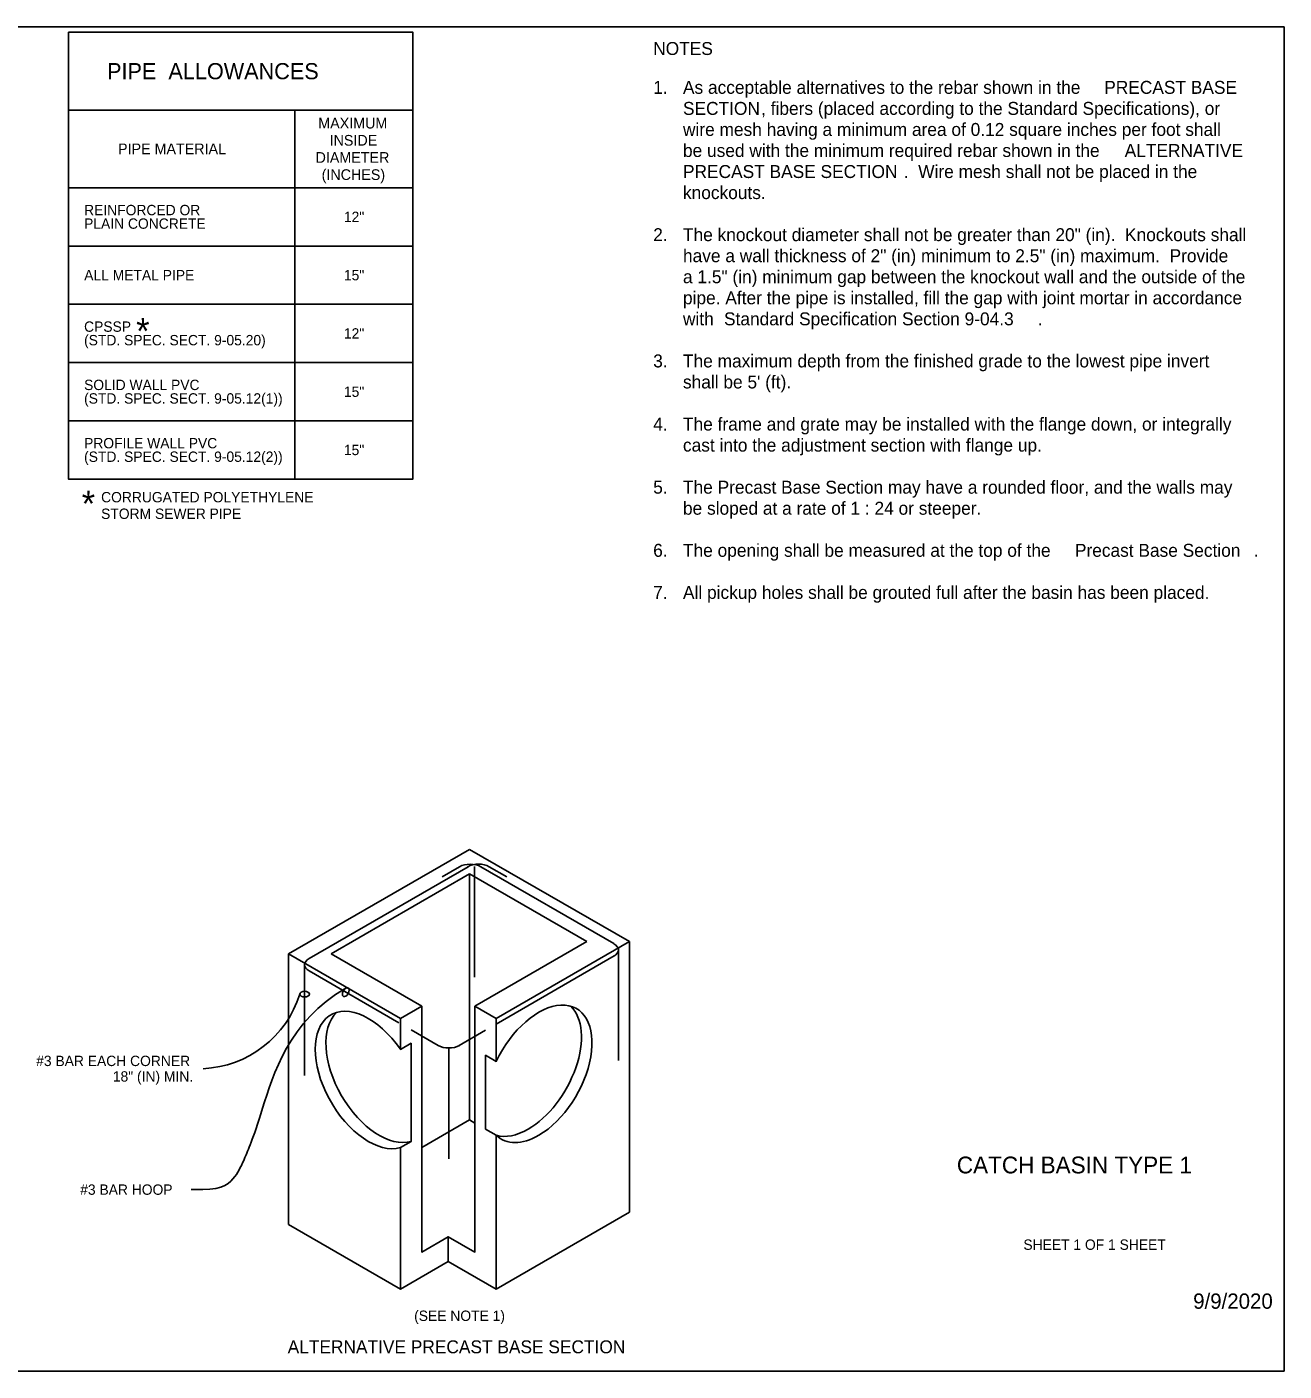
# Model space of a CAD drawing. Extents: x 99862 to 103151, y 100000 to 102076.
# Drawn here: x 101209 to 103151, y 100000 to 102076 of the extents above; entities that cross this region are included whole.
import ezdxf

# ---------------------------------------------------------------- set-up
doc = ezdxf.new("R2010")
doc.units = 0
for name, color, linetype in [('Level 1', 7, 'Continuous'), ('Level 15', 7, 'Continuous'), ('Level 17', 7, 'Continuous'), ('Level 19', 7, 'Continuous'), ('Level 20', 7, 'Continuous'), ('Level 34', 7, 'Continuous'), ('Level 40', 7, 'Continuous'), ('Level 44', 7, 'Continuous'), ('Level 60', 7, 'Continuous'), ('Level 62', 7, 'Continuous')]:
    doc.layers.add(name, color=color, linetype=linetype)

msp = doc.modelspace()

# ---------------------------------------------------------------- linework, layer by layer
at = {"layer": 'Level 1'}
for p, q in [((101613.1, 100643.8), (101892.7, 100805.3)), ((101892.7, 100805.3), (102139.5, 100662.8)), ((101892.7, 100767.3), (101678.9, 100643.8)), ((102073.6, 100662.8), (101892.7, 100767.3)), ((101892.7, 100767.3), (101892.7, 100387.4)), ((101900.9, 100563.1), (102073.6, 100662.8)), ((102139.5, 100662.8), (101933.8, 100544.1)), ((102139.5, 100662.8), (102139.5, 100244.9)), ((101785.8, 100544.1), (101613, 100643.8)), ((101613.1, 100643.8), (101613.1, 100225.9)), ((101678.9, 100643.8), (101818.7, 100563.1)), ((101818.7, 100344.6), (101892.7, 100387.4)), ((101900.9, 100382.6), (101892.7, 100387.4)), ((101933.8, 100126.2), (102139.5, 100244.9)), ((101613.1, 100225.9), (101785.8, 100126.2))]:
    msp.add_line(p, q, dxfattribs=at)
msp.add_lwpolyline([(99862, 99999.5), (103151, 99999.5), (103151, 102075.5), (99862, 102075.5)], close=True, dxfattribs=at)
for centre, major_axis, start_param, end_param in [((101736.4, 100449.1), (-58.1, 100.7), 4.853387, 9.28378), ((101999.6, 100458.7), (58.1, 100.7), 3.926991, 7.995826), ((101983.2, 100468.1), (58.1, 100.7), 3.926991, 6.141613), ((101752.9, 100458.6), (-58.1, 100.7), 0.144003, 3.001512), ((101983.2, 100468.1), (58.1, 100.7), 3.282336, 3.926991), ((101999.6, 100458.7), (58.1, 100.7), 2.999618, 3.926991)]:
    msp.add_ellipse(centre, major_axis=major_axis, ratio=0.57735, start_param=start_param, end_param=end_param, dxfattribs=at)
at = {"layer": 'Level 15'}
msp.add_line((101462.5, 100279.8), (101480.6, 100279.8), dxfattribs=at)
msp.add_arc((101473.8, 100630.2), 163.8, 272.625, 342.7664, dxfattribs=at)
for centre, major_axis in [((101637.7, 100581.7), (-7.5, 0)), ((101701.4, 100584.8), (3.75, 6.5))]:
    msp.add_ellipse(centre, major_axis=major_axis, ratio=0.57735, dxfattribs=at)
msp.add_open_spline([(101701.5, 100591), (101613.3, 100540.3), (101563.8, 100370.8), (101544.1, 100325.8), (101533.3, 100301.1), (101512.4, 100279.8), (101480.6, 100279.8)], degree=3, dxfattribs=at)
at = {"layer": 'Level 17'}
for p, q in [((101802.2, 100526.6), (101843.9, 100502.5)), ((101876.8, 100502.5), (101917.4, 100525.9)), ((101860.4, 100498.6), (101860.4, 100327.6))]:
    msp.add_line(p, q, dxfattribs=at)
msp.add_ellipse((101860.4, 100512), major_axis=(23.3, 0), ratio=0.57735, start_param=3.926991, end_param=5.497787, dxfattribs=at)
at = {"layer": 'Level 34'}
for p, q in [((101877.2, 100778.4), (101850.1, 100762.8)), ((101900.2, 100778.6), (101900.2, 100607.7)), ((101923.1, 100778.5), (101950.1, 100762.8)), ((102122.8, 100652), (102122.8, 100479.2)), ((101637.7, 100627.1), (101637.7, 100456.1)), ((101933.8, 100535.4), (102116, 100640.6)), ((101783.2, 100537.5), (101644.6, 100617.5))]:
    msp.add_line(p, q, dxfattribs=at)
for points in [[(101644.6, 100636.7), (101890.2, 100778.5)], [(102115.7, 100659.7), (101910.1, 100778.4)]]:
    msp.add_lwpolyline(points, dxfattribs=at)
for centre, major_axis, start_param, end_param in [((101893.7, 100768.9), (23.3, 0), 0.785398, 2.356194), ((101906.6, 100769), (-23.3, 0), 3.926991, 5.497787), ((102099, 100649.9), (23.5, 0), 5.497787, 7.068583), ((101661.3, 100627.1), (-23.5, 0), 5.497787, 7.068583)]:
    msp.add_ellipse(centre, major_axis=major_axis, ratio=0.57735, start_param=start_param, end_param=end_param, dxfattribs=at)
at = {"layer": 'Level 40'}
for p, q in [((101622.8, 101947.1), (101622.8, 101377.1)), ((101273, 101827.1), (101805, 101827.1)), ((101273, 101737.1), (101805, 101737.1)), ((101273, 101647.1), (101805, 101647.1)), ((101273, 101557.1), (101805, 101557.1)), ((101273, 101467.1), (101805, 101467.1))]:
    msp.add_line(p, q, dxfattribs=at)
for points in [[(101273, 102067.1), (101805, 102067.1), (101805, 101947.1), (101273, 101947.1)], [(101273, 101947.1), (101805, 101947.1), (101805, 101377.1), (101273, 101377.1)]]:
    msp.add_lwpolyline(points, close=True, dxfattribs=at)
at = {"layer": 'Level 44'}
msp.add_lwpolyline([(101785.8, 100496.5), (101785.8, 100496.5), (101785.8, 100496.4), (101802.3, 100505.9), (101802.4, 100354.2), (101802.3, 100354.2), (101785.8, 100344.6), (101785.8, 100126.2), (101859.8, 100168.9), (101859.8, 100207), (101818.7, 100183.3), (101818.7, 100344.6), (101818.7, 100563.1), (101785.8, 100544.1), (101785.8, 100496.5)], dxfattribs=at)
msp.add_lwpolyline([(101900.9, 100371.4), (101900.9, 100183.3), (101859.8, 100207), (101859.8, 100168.9), (101933.8, 100126.2), (101933.8, 100363.7), (101917.4, 100373.2), (101917.4, 100487.2), (101933.8, 100477.7), (101933.8, 100544.1), (101900.9, 100563.1)], close=True, dxfattribs=at)
msp.add_ellipse((101736.4, 100449.1), major_axis=(-58.1, 100.7), ratio=0.57735, start_param=4.853387, end_param=4.853404, dxfattribs=at)
at = {"layer": 'Level 60'}
msp.add_line((103151, 102075.5), (103151, 102075.5), dxfattribs=at)
msp.add_line((103151, 102075.5), (103151, 102075.5), dxfattribs=at)
msp.add_line((103151, 102075.5), (103151, 102075.5), dxfattribs=at)

# ---------------------------------------------------------------- texts
at = {"layer": 'Level 15'}
msp.add_text('9/9/2020', height=23.62, dxfattribs=at).set_placement((103010.5, 100095.8))
at = {"layer": 'Level 19'}
msp.add_text('PIPE  ALLOWANCES', height=25, dxfattribs=at).set_placement((101332.6, 101994.6))
at = {"layer": 'Level 20'}
for s, height, p in [('NOTES', 20, (102176.3, 102032.1)), ('1.', 20, (102176.3, 101972.1)), ('As acceptable alternatives to the rebar shown in the ', 20, (102222.3, 101972.1)), ('PRECAST BASE', 20, (102873.1, 101972.1)), ('SECTION', 20, (102222.3, 101939.6)), (', fibers (placed according to the Standard Specifications), or', 20, (102343, 101939.6)), ('MAXIMUM', 16.5, (101658.9, 101918.6)), ('wire mesh having a minimum area of 0.12 square inches per foot shall', 20, (102222.3, 101907.1)), ('PIPE MATERIAL', 16.5, (101349.6, 101878.9)), ('INSIDE', 16.5, (101676.4, 101892.1)), ('be used with the minimum required rebar shown in the ', 20, (102222.3, 101874.6)), ('ALTERNATIVE', 20, (102904.7, 101874.6)), ('DIAMETER', 16.5, (101654.7, 101865.6)), ('(INCHES)', 16.5, (101664.1, 101839.1)), ('PRECAST BASE SECTION', 20, (102222.3, 101842.1)), ('.  Wire mesh shall not be placed in the', 20, (102563.4, 101842.1)), ('knockouts.', 20, (102222.3, 101809.6)), ('REINFORCED OR', 16, (101297.1, 101784.6)), ('12"', 16, (101698.5, 101774.1)), ('PLAIN CONCRETE', 16, (101297.1, 101763.7)), ('The knockout diameter shall not be greater than 20" (in).  Knockouts shall', 20, (102222.3, 101744.6)), ('2.', 20, (102176.3, 101744.6)), ('have a wall thickness of 2" (in) minimum to 2.5" (in) maximum.  Provide', 20, (102222.3, 101712.1)), ('ALL METAL PIPE', 16, (101297.3, 101684.1)), ('15"', 16, (101698.5, 101684.1)), ('a 1.5" (in) minimum gap between the knockout wall and the outside of the', 20, (102222.3, 101679.6)), ('pipe. After the pipe is installed, fill the gap with joint mortar in accordance', 20, (102222.3, 101647.1)), ('CPSSP', 16, (101297.1, 101604.6)), ('*', 40, (101377.5, 101585.8)), ('with ', 20, (102222.3, 101614.6)), ('Standard Specification Section 9-04.3', 20, (102285.7, 101614.6)), ('(STD. SPEC. SECT. 9-05.20)', 16, (101297.1, 101583.7)), ('12"', 16, (101698.5, 101594.1)), ('.', 20, (102770.3, 101614.6)), ('3.', 20, (102176.3, 101549.6)), ('The maximum depth from the finished grade to the lowest pipe invert', 20, (102222.3, 101549.6)), ("shall be 5' (ft).", 20, (102222.3, 101517.1)), ('SOLID WALL PVC', 16, (101297.1, 101514.6)), ('15"', 16, (101698.5, 101504.1)), ('(STD. SPEC. SECT. 9-05.12(1))', 16, (101297.1, 101493.7)), ('4.', 20, (102176.3, 101452.1)), ('The frame and grate may be installed with the flange down, or integrally', 20, (102222.3, 101452.1)), ('PROFILE WALL PVC', 16, (101297.1, 101424.6)), ('cast into the adjustment section with flange up.', 20, (102222.3, 101419.6)), ('(STD. SPEC. SECT. 9-05.12(2))', 16, (101297.1, 101403.7)), ('15"', 16, (101698.5, 101414.1)), ('5.', 20, (102176.3, 101354.6)), ('The Precast Base Section may have a rounded floor, and the walls may', 20, (102222.3, 101354.6)), ('*', 40, (101293.4, 101319.2)), ('CORRUGATED POLYETHYLENE', 16, (101323.4, 101341.2)), ('STORM SEWER PIPE', 16, (101323.4, 101315.6)), ('be sloped at a rate of 1 : 24 or steeper.', 20, (102222.3, 101322.1)), ('6.', 20, (102176.3, 101257.1)), ('The opening shall be measured at the top of the ', 20, (102222.3, 101257.1)), ('Precast Base Section', 20, (102827.8, 101257.1)), ('.', 20, (103104.1, 101257.1)), ('7.', 20, (102176.3, 101192.1)), ('All pickup holes shall be grouted full after the basin has been placed.', 20, (102222.3, 101192.1)), ('#3 BAR EACH CORNER', 16, (101223.1, 100470.6)), ('18" (IN) MIN.', 16, (101341.5, 100446.6)), ('#3 BAR HOOP', 16, (101291.1, 100271.8)), ('(SEE NOTE 1)', 16, (101807, 100077)), ('ALTERNATIVE PRECAST BASE SECTION', 20, (101611.6, 100027))]:
    msp.add_text(s, height=height, dxfattribs=at).set_placement(p)
at = {"layer": 'Level 62'}
for s, height, p in [('CATCH BASIN TYPE 1', 26, (102645.4, 100304.8)), ('SHEET 1 OF 1 SHEET', 16, (102748.2, 100186.8))]:
    msp.add_text(s, height=height, dxfattribs=at).set_placement(p)

doc.saveas('drawing.dxf')
